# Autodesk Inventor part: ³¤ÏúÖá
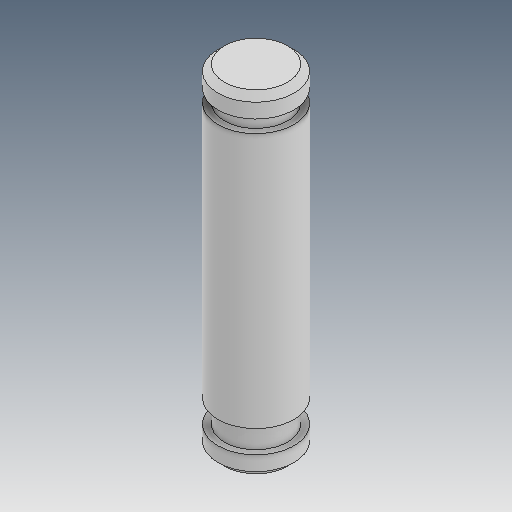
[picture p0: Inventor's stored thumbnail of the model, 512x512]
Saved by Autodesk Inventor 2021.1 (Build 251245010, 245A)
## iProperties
Created: 2019-04
Part Number: ³¤ÏúÖá
Material: Ogólny
Document SubType Name: Modeling
Designer: user
Density: 1 g/cm^3
Appearance: Domyślna
Author: user
Revision Number: ÈÎºÎ
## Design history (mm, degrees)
feature "ÊäÈë1"
node "Bryła1"
